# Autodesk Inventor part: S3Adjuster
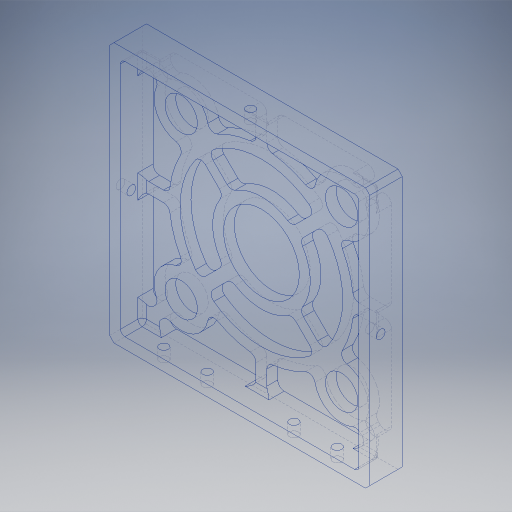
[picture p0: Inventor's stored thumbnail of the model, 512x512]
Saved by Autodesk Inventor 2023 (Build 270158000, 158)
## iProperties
Created: 2024-01
Part Number: S3Adjuster
Material: Aluminum 6061
Document SubType Name: Modeling
Designer: tornqvih
Density: 2.7 g/cm^3
Appearance: Aluminum - Flat
Author: tornqvih
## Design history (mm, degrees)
sketch "Sketch1"
  geometry: L1 (-60, 60)-(60, 60); L2 (60, 60)-(60, -60); L3 (60, -60)-(-60, -60); L4 (-60, -60)-(-60, 60); L5 (-60, 60)-(60, -60); L6 (60, 60)-(-60, -60); L7 (-51.464, 55)-(-14.044, 17.579); L8 (51.464, 55)-(14.044, 17.579); L9 (-55, 51.464)-(-17.579, 14.044); L10 (-55, -51.464)-(-17.579, -14.044); L11 (-51.464, -55)-(-14.044, -17.579); L12 (14.044, -17.579)-(51.464, -55); L13 (17.579, 14.044)-(55, 51.464); L14 (17.579, -14.044)-(55, -51.464); L15 (-84, 0)-(84, 0) reference; L16 (0, -84)-(0, 84) reference; L17 (-55, 55)-(55, 55); L18 (55, 55)-(55, -55); L19 (55, -55)-(-55, -55); L20 (-55, -55)-(-55, 55); L21 (-55, 55)-(55, -55); L22 (55, 55)-(-55, -55); L23 (-2.5, 55)-(-2.5, 42.426); L24 (2.5, 55)-(2.5, 42.426); L25 (-55, 2.5)-(-42.426, 2.5); L26 (-55, -2.5)-(-42.426, -2.5); L27 (-2.5, -55)-(-2.5, -42.426); L28 (2.5, -55)-(2.5, -42.426); L29 (55, 2.5)-(42.426, 2.5); L30 (55, -2.5)-(42.426, -2.5); C1 r 17.5 at (0, 0); C2 r 37.5 at (0, 0); C3 r 7.5 at (-37, 37); C4 r 7.5 at (37, 37); C5 r 7.5 at (37, -37); C6 r 7.5 at (-37, -37); C7 r 12.5 at (-37, 37); C8 r 12.5 at (37, 37); C9 r 12.5 at (-37, -37); C10 r 12.5 at (37, -37); 45 further points
  constraints: 56 end point, 28 symmetric about line, 23 point on line, 10 centre point, 8 coincident, 6 equal radius, 6 parallel, 4 midpoint, 3 perpendicular, 2 horizontal, 20 other
  dimensions: "d0" = 120 distance of L1.start L1.end; "d48" = 35 diameter of C1; "d50" = 75 diameter of C2; "d53" = 15 diameter of C3; "d55" = 5 distance between parallel lines of L7 L9; "d57" = 37 distance from line of L16 C3.centre; "d58" = 5 dimension on C1; "d59" = 5 dimension on C2; "d60" = 110 distance of L17.start L17.end; "d61" = 5 radial gap between concentric circles of C7 C3; "d63" = 5 distance between parallel lines of L24 L23
extrude "Extrusion1" new body sketch "Sketch1" distance "d1" = 15; taper "d2" = 0 deg
sketch "Sketch2"
  geometry: L1 (-55, -55)-(55, -55); L2 (55, -55)-(55, 55); L3 (55, 55)-(-55, 55); L4 (-55, 55)-(-55, -55); L5 (-55, -55)-(55, 55); L6 (55, -55)-(-55, 55); 1 further point
  constraints: 12 end point, 2 midpoint, 2 parallel, 2 perpendicular, 1 horizontal
  dimensions: "d3" = 110 distance of L2.end L3.end
extrude "Extrusion2" cut sketch "Sketch2" distance "d4" = 10; taper "d5" = 0 deg
sketch "Sketch3"
  geometry: L1 (120, 0)-(0, 0) reference; L2 (120, -15)-(0, -15) reference; 3 further points
  constraints: 1 midpoint, 1 vertical alignment
  dimensions: "d6" = 5 distance from line of L2 point (60, -10)
hole "Hole1" sketch "Sketch3" at (60, -10) diameter "d7" = 4.134; stored, may be unused: countersink angle "d11" = 90 deg, drill point angle "d13" = 118 deg; dims "d8" = 10, "d9" = 4, "d10" = 2, "d12" = 14.2
sketch "Sketch4"
  geometry: L1 (0, 0)-(0, 120) reference; L2 (-15, 0)-(-15, 120) reference; 3 further points
  constraints: 1 horizontal alignment, 1 midpoint
  dimensions: "d14" = 5 distance from line of L2 point (-10, 60)
hole "Hole2" sketch "Sketch4" at (-10, 60) diameter "d15" = 4.134; stored, may be unused: countersink angle "d19" = 90 deg, drill point angle "d21" = 118 deg; dims "d16" = 10, "d17" = 4, "d18" = 2, "d20" = 8
sketch "Sketch5"
  geometry: C1 r 2.067 at (10, 60) reference; 2 further points
  constraints: 1 coincident
hole "Hole3" sketch "Sketch5" at (10, 60) diameter "d22" = 4.134; stored, may be unused: countersink angle "d26" = 90 deg, drill point angle "d28" = 118 deg; dims "d23" = 10, "d24" = 4, "d25" = 2, "d27" = 8
sketch "Sketch6"
  geometry: L1 (0, 0)-(120, 0) reference; L2 (0, 15)-(120, 15) reference; L3 (120, 0)-(0, 0) reference; 9 further points
  constraints: 4 midpoint, 3 horizontal alignment
  dimensions: "d29" = 40 horizontal distance of point (60, 0) point (20, 10); "d30" = 40 horizontal distance of point (60, 0) point (100, 10); "d31" = 5 distance from line of L2 point (20, 10); "d69" = 20 horizontal distance of point (60, 0) point (40, 10); "d70" = 20 horizontal distance of point (60, 0) point (80, 10)
hole "Hole4" sketch "Sketch6" at (20, 10), (40, 10), (80, 10), (100, 10) diameter "d32" = 4.134; stored, may be unused: countersink angle "d36" = 90 deg, drill point angle "d38" = 118 deg; dims "d33" = 10, "d34" = 4, "d35" = 2, "d37" = 8
fillet "Fillet1" dims "d64" = 3, "d68" = 2
chamfer "Chamfer1" distance "d65" = 2; stored, may be unused: second distance "d66" = 2, angle "d67" = 45 deg
body "Solid1"
